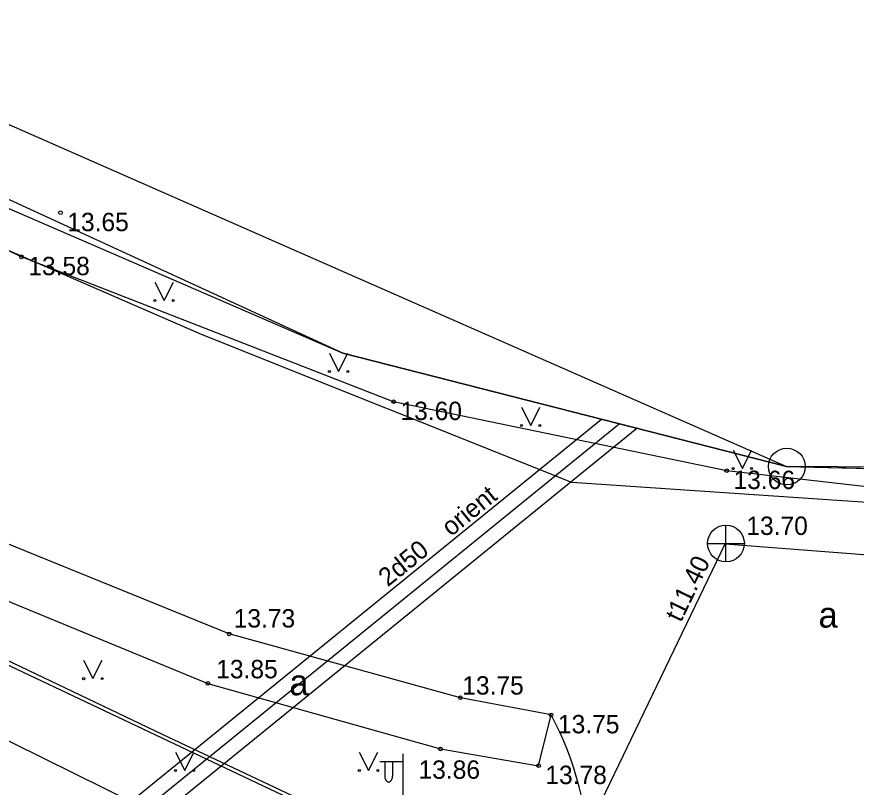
# Model space of a CAD drawing. Extents: x 503904 to 504094, y 304688 to 304960.
# Drawn here: x 504027.93 to 504050.77, y 304877.05 to 304898.01 of the extents above; entities that cross this region are included whole.
import ezdxf

# ---------------------------------------------------------------- set-up
doc = ezdxf.new("R2010")
doc.units = 0
for name, color, linetype in [('APGR_ELEM_####_####_#', 7, 'Continuous'), ('APGR_SARK_####_####_#', 7, 'Continuous'), ('APGS_ELEM_####_####_#', 7, 'Continuous'), ('APGS_VADP_ZSPR_####_#', 7, 'Continuous'), ('CELI_CAPM_####_####_#', 7, 'Continuous'), ('CELI_CMAL_####_####_#', 7, 'Continuous'), ('CELI_CSEG_####_TKST_#', 7, 'Continuous'), ('GAZE_VADP_VSP2_####_#', 7, 'Continuous'), ('RAMI_UZMR_####_####_#', 7, 'Continuous'), ('RELJ_AATZ_####_TKST_#', 7, 'Continuous'), ('RELJ_ELEM_####_####_#', 7, 'Continuous'), ('ROBZ_UZMR_####_####_#', 7, 'Continuous'), ('SILT_VADP_NEDR_####_#', 7, 'Continuous'), ('SILT_VADP_NEDR_TKST_#', 7, 'Continuous'), ('SILT_VADP_UDEN_TKAM_#', 7, 'Continuous'), ('SKAN_ELEM_####_####_#', 7, 'Continuous'), ('SKAN_ELEM_PAST_TKST_#', 7, 'Continuous'), ('SKAN_VADP_PAST_####_I', 7, 'Continuous'), ('SKAN_VADP_PAST_TKST_I', 7, 'Continuous'), ('TERT_ELEM_####_####_#', 7, 'Continuous'), ('UDTK_VADP_UDEN_####_#', 7, 'Continuous')]:
    doc.layers.add(name, color=color, linetype=linetype)

msp = doc.modelspace()

# ---------------------------------------------------------------- linework, layer by layer
at = {"layer": 'APGR_ELEM_####_####_#'}
msp.add_circle((504048.88, 304885.77), 0.5, dxfattribs=at)
at = {"layer": 'APGR_SARK_####_####_#'}
for p, q in [((503977.453, 304917.18), (504048.875, 304885.773)), ((504048.875, 304885.773), (504074.071, 304885.171))]:
    msp.add_line(p, q, dxfattribs=at)
at = {"layer": 'APGS_ELEM_####_####_#'}
for p, q in [((504038.443, 304876.071), (504038.443, 304877.954)), ((504038.443, 304877.738), (504037.808, 304877.733)), ((504037.943, 304877.734), (504037.943, 304877.342)), ((504038.153, 304877.736), (504038.153, 304877.342))]:
    msp.add_line(p, q, dxfattribs=at)
msp.add_ellipse((504038.048, 304877.342), major_axis=(0, 0.151), ratio=0.695971, start_param=1.570796, end_param=4.712389, dxfattribs=at)
at = {"layer": 'APGS_VADP_ZSPR_####_#'}
for points in [[(504034.948, 304837.203), (504032.464, 304838.354), (504032.46, 304838.624), (504032.497, 304838.963), (504034.767, 304843.029), (504037.037, 304847.095), (504041.785, 304855.598), (504046.532, 304864.101), (504046.909, 304866.055), (504048.051, 304868.025), (504049.192, 304869.995), (504049.205, 304870.202), (504049.157, 304870.343), (504042.295, 304873.577), (504035.433, 304876.812), (504031.898, 304878.478), (504020.359, 304883.989), (504008.82, 304889.499), (504008.617, 304889.54), (504008.431, 304889.443), (504006.058, 304885.968)], [(504006.081, 304886.016), (504006.524, 304886.457), (504007.485, 304887.87), (504008.446, 304889.284), (504008.616, 304889.405), (504008.824, 304889.386), (504016.168, 304885.866), (504023.512, 304882.345), (504029.465, 304879.528), (504035.491, 304876.677), (504037.943, 304875.532), (504038.212, 304875.634), (504038.416, 304876.08), (504038.226, 304875.558), (504038.331, 304875.343), (504039.638, 304874.712), (504041.796, 304873.674), (504045.914, 304871.662), (504049.181, 304870.056), (504051.511, 304869.798), (504052.144, 304869.735)]]:
    msp.add_lwpolyline(points, dxfattribs=at)
at = {"layer": 'CELI_CAPM_####_####_#'}
msp.add_lwpolyline([(504042.469, 304879.012), (504039.999, 304879.481), (504033.709, 304881.219), (504024.994, 304884.76), (504014.798, 304889.372), (504004.157, 304894.141)], dxfattribs=at)
at = {"layer": 'CELI_CMAL_####_####_#'}
for points in [[(504056.369, 304885.722), (504054.86, 304884.787), (504047.246, 304885.659), (504038.184, 304887.536), (504028.058, 304891.478), (504020.037, 304895.213), (504011.327, 304899.02)], [(504004.157, 304894.141), (504003.635, 304892.793), (504014.253, 304888.009), (504024.188, 304883.551), (504033.132, 304879.868), (504039.457, 304878.088), (504042.126, 304877.631), (504042.469, 304879.012)]]:
    msp.add_lwpolyline(points, dxfattribs=at)
msp.add_arc((504034.812, 304874.895), 8.694, 0.5576, 28.2626, dxfattribs=at)
at = {"layer": 'GAZE_VADP_VSP2_####_#'}
msp.add_lwpolyline([(503989.698, 304903.414), (504000, 304898.037), (504010.212, 304892.707), (504011.048, 304889.414), (504011.884, 304886.121), (504025.295, 304879.492), (504038.706, 304872.862), (504042.754, 304870.726), (504047.158, 304868.745), (504052.063, 304869.587)], dxfattribs=at)
at = {"layer": 'RAMI_UZMR_####_####_#'}
msp.add_lwpolyline([(503923.253, 304801.015), (503981.982, 304759.672), (503995.48, 304748.813), (504027.75, 304817.255), (504060.02, 304885.696), (504048.875, 304885.773), (504036.803, 304888.853), (503994.536, 304908.303), (503981.123, 304894.75), (503978.518, 304892.436), (503950.886, 304846.726), (503923.253, 304801.015)], dxfattribs=at)
at = {"layer": 'RELJ_ELEM_####_####_#'}
for centre in [(504029.119, 304892.676), (504028.058, 304891.478), (504038.184, 304887.536), (504047.246, 304885.659), (504033.709, 304881.219), (504033.132, 304879.868), (504039.999, 304879.481), (504042.469, 304879.012), (504039.457, 304878.088), (504042.126, 304877.631)]:
    msp.add_circle(centre, 0.05, dxfattribs=at)
at = {"layer": 'ROBZ_UZMR_####_####_#'}
msp.add_lwpolyline([(503976.959, 304916.696), (503989.759, 304910.584), (503994.536, 304908.303), (504011.531, 304900.187), (504020.191, 304896.051), (504036.803, 304888.853), (504048.875, 304885.773), (504074.124, 304885.169)], dxfattribs=at)
at = {"layer": 'SILT_VADP_NEDR_####_#'}
msp.add_lwpolyline([(504022.461, 304869.185), (504044.321, 304886.935)], dxfattribs=at)
at = {"layer": 'SILT_VADP_UDEN_TKAM_#'}
for points in [[(504021.948, 304869.284), (504043.838, 304887.058)], [(504022.974, 304869.086), (504044.804, 304886.812)]]:
    msp.add_lwpolyline(points, dxfattribs=at)
at = {"layer": 'SKAN_ELEM_####_####_#'}
for p, q in [((504047.226, 304883.178), (504047.226, 304884.178)), ((504046.726, 304883.678), (504047.726, 304883.678))]:
    msp.add_line(p, q, dxfattribs=at)
msp.add_circle((504047.226, 304883.678), 0.5, dxfattribs=at)
at = {"layer": 'SKAN_VADP_PAST_####_I'}
msp.add_lwpolyline([(504023.783, 304835.985), (504032.733, 304853.578), (504047.208, 304883.667), (504054.39, 304883.114), (504058.648, 304882.787)], dxfattribs=at)
at = {"layer": 'TERT_ELEM_####_####_#'}
for p, q in [((504031.69, 304890.788), (504031.94, 304890.288)), ((504031.94, 304890.288), (504032.19, 304890.788)), ((504036.435, 304888.86), (504036.685, 304888.36)), ((504036.685, 304888.36), (504036.935, 304888.86)), ((504041.664, 304887.39), (504041.914, 304886.89)), ((504041.914, 304886.89), (504042.164, 304887.39)), ((504047.422, 304886.215), (504047.672, 304885.715)), ((504047.672, 304885.715), (504047.922, 304886.215)), ((504029.75, 304880.5), (504030, 304880)), ((504030, 304880), (504030.25, 304880.5)), ((504032.25, 304878), (504032.5, 304877.5)), ((504032.5, 304877.5), (504032.75, 304878)), ((504037.25, 304878), (504037.5, 304877.5)), ((504037.5, 304877.5), (504037.75, 304878))]:
    msp.add_line(p, q, dxfattribs=at)
for centre, radius in [((504031.689, 304890.288), 0.028), ((504032.189, 304890.288), 0.0263), ((504036.435, 304888.36), 0.028), ((504036.935, 304888.36), 0.0263), ((504041.664, 304886.889), 0.028), ((504042.164, 304886.889), 0.0263), ((504047.421, 304885.715), 0.028), ((504047.921, 304885.715), 0.0263), ((504029.75, 304880), 0.028), ((504030.25, 304880), 0.0263), ((504032.25, 304877.5), 0.028), ((504032.75, 304877.5), 0.0263), ((504037.25, 304877.5), 0.028), ((504037.75, 304877.5), 0.0263)]:
    msp.add_circle(centre, radius, dxfattribs=at)
at = {"layer": 'UDTK_VADP_UDEN_####_#'}
msp.add_lwpolyline([(504059.328, 304884.23), (504052.534, 304884.693), (504043.033, 304885.34), (504032.956, 304889.369), (504014.268, 304897.491), (504000, 304903.846), (503993.127, 304906.879)], dxfattribs=at)

# ---------------------------------------------------------------- texts
at = {"layer": 'CELI_CSEG_####_TKST_#'}
for p in [(504049.745, 304881.388), (504035.347, 304879.548)]:
    msp.add_text('a', height=0.7, dxfattribs=at).set_placement(p)
at = {"layer": 'RELJ_AATZ_####_TKST_#'}
for s, p in [(' 13.65', (504029.119, 304892.176)), (' 13.58', (504028.058, 304890.978)), (' 13.60', (504038.184, 304887.036)), (' 13.66', (504047.246, 304885.159)), (' 13.73', (504033.646, 304881.391)), (' 13.85', (504033.171, 304880.009)), (' 13.75', (504039.865, 304879.566)), (' 13.75', (504042.469, 304878.512)), (' 13.86', (504038.675, 304877.275)), (' 13.78', (504042.126, 304877.131))]:
    msp.add_text(s, height=0.5, dxfattribs=at).set_placement(p)
at = {"layer": 'SILT_VADP_NEDR_TKST_#'}
for s, p in [('orient', (504039.744, 304883.851)), ('2d50', (504038.025, 304882.484))]:
    msp.add_text(s, height=0.5, rotation=39.0758, dxfattribs=at).set_placement(p)
at = {"layer": 'SKAN_ELEM_PAST_TKST_#'}
msp.add_text('13.70', height=0.5, dxfattribs=at).set_placement((504047.78, 304883.91))
at = {"layer": 'SKAN_VADP_PAST_TKST_I'}
msp.add_text('t11.40', height=0.5, rotation=64.2071, dxfattribs=at).set_placement((504045.999, 304881.509))

doc.saveas('drawing.dxf')
